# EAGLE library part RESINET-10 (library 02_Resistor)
Resistor Network(10) 10 peaces
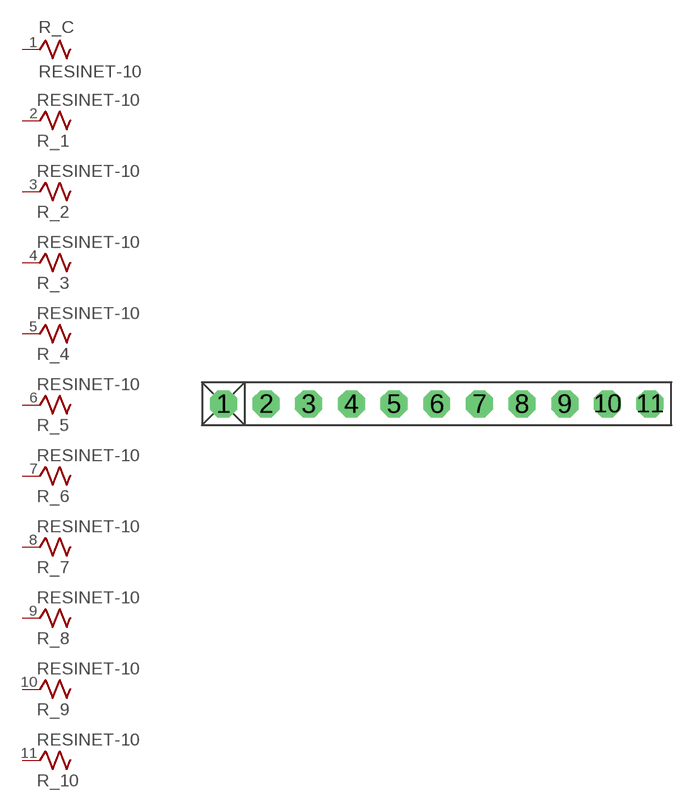
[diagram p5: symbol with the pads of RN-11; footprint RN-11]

Designator prefix R; gates _C=RESINET-COM _1=RESINET-X _2=RESINET-X _3=RESINET-X _4=RESINET-X _5=RESINET-X _6=RESINET-X _7=RESINET-X _8=RESINET-X _9=RESINET-X _10=RESINET-X

## RESINET-10  [RN-11]
1  _C:1  pas
2  _1:1  pas
3  _2:1  pas
4  _3:1  pas
5  _4:1  pas
6  _5:1  pas
7  _6:1  pas
8  _7:1  pas
9  _8:1  pas
10  _9:1  pas
11  _10:1  pas

## Footprint RN-11 (pad centres in mm)
Resistor Network(10) 10 peaces
drill 0.813 pad 1.6 octagon: 1 -12.7,0; 2 -10.16,0; 3 -7.62,0; 4 -5.08,0; 5 -2.54,0; 6 0,0; 7 2.54,0; 8 5.08,0; 9 7.62,0; 10 10.16,0; 11 12.7,0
